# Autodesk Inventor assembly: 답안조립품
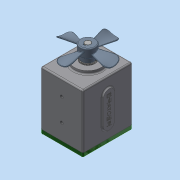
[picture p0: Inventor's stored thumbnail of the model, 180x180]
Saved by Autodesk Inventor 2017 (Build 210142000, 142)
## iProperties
Part Number: 답안조립품
Material: 일반
Document SubType Name: Assembly
Designer: MRC
Author: MRC
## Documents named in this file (17)
- C:\Users\MRC\Desktop\610205V1005\답안조립품.iam
- C:\Users\MRC\Desktop\610205V1005\본체.ipt
- C:\Users\MRC\Desktop\610205V1005\가변스프링.ipt
- C:\Users\MRC\Desktop\610205V1005\멈춤나사 M3x8.ipt
- C:\Users\MRC\Desktop\610205V1005\메인 기어 축.ipt
- C:\Users\MRC\Desktop\610205V1005\베어링 608.ipt
- C:\Users\MRC\Desktop\610205V1005\베어링 6903.ipt
- C:\Users\MRC\Desktop\610205V1005\볼트 M4 x 10.ipt
- C:\Users\MRC\Desktop\610205V1005\부시.ipt
- C:\Users\MRC\Desktop\610205V1005\서브 기어 축.ipt
- C:\Users\MRC\Desktop\610205V1005\슬라이더.ipt
- C:\Users\MRC\Desktop\610205V1005\오일 실 8 22 7.ipt
- C:\Users\MRC\Desktop\610205V1005\오일 실 17 30 8.ipt
- C:\Users\MRC\Desktop\610205V1005\커버.ipt
- C:\Users\MRC\Desktop\610205V1005\키 5 x 5 x 24.ipt
- C:\Users\MRC\Desktop\610205V1005\팬날개.ipt
- 팬날개.ipt
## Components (1 placed, 1 different names)
1. 가변스프링:1
